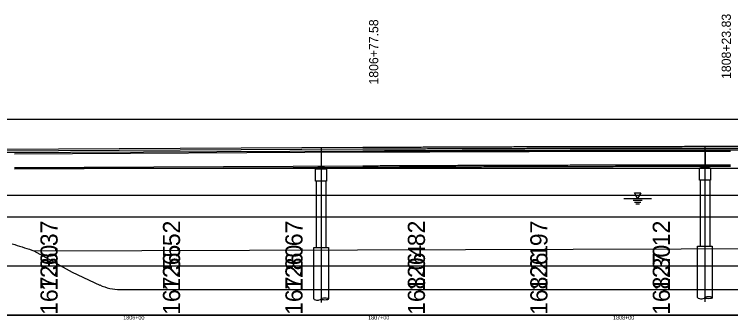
# Model space of a CAD drawing. Extents: x 2126510 to 2136144, y 865066 to 868066.
# Drawn here: x 2133154.3 to 2133446.8, y 867812.5 to 867937.3 of the extents above; entities that cross this region are included whole.
import ezdxf

# ---------------------------------------------------------------- set-up
doc = ezdxf.new("R2010")
doc.units = 0
for name, color, linetype in [('RD_DTM_BkLn1', 7, 'Continuous'), ('RD_EX_BldgApp', 7, 'Continuous'), ('RD_EX_Bridge', 7, 'Continuous'), ('RD_EX_GuardRail', 7, 'Continuous'), ('RD_EX_H2O', 7, 'Continuous'), ('RD_EX_Misc', 7, 'Continuous'), ('RD_EX_UT', 7, 'Continuous'), ('RD_HC_Data', 7, 'Continuous'), ('RD_HC_txCode', 7, 'Continuous')]:
    doc.layers.add(name, color=color, linetype=linetype)

msp = doc.modelspace()

# ---------------------------------------------------------------- linework, layer by layer
at = {"layer": 'RD_DTM_BkLn1'}
for p, q in [((2132861.9, 867879.34), (2133296.65, 867881.51)), ((2133281.33, 867874.43), (2133277.83, 867874.43)), ((2133277.83, 867874.43), (2133277.83, 867874.09)), ((2133280.91, 867874.72), (2133278.24, 867874.72)), ((2133278.24, 867874.43), (2133280.91, 867874.43)), ((2133281.33, 867874.09), (2133281.33, 867874.43)), ((2133434.58, 867874.9), (2133434.58, 867874.56)), ((2133435.99, 867874.9), (2133434.58, 867874.9)), ((2133434.99, 867874.9), (2133437.66, 867874.9)), ((2133438.08, 867874.9), (2133436.33, 867874.9)), ((2133438.08, 867874.56), (2133438.08, 867874.9)), ((2133277.58, 867869.09), (2133277.58, 867841.96)), ((2133281.58, 867869.09), (2133281.58, 867841.96)), ((2133434.33, 867869.56), (2133434.33, 867842.5)), ((2133438.33, 867869.56), (2133438.33, 867842.5))]:
    msp.add_line(p, q, dxfattribs=at)
for points in [[(2133277.33, 867874.09), (2133281.83, 867874.09), (2133281.83, 867869.09), (2133277.33, 867869.09)], [(2133434.08, 867874.56), (2133438.58, 867874.56), (2133438.58, 867869.56), (2133434.08, 867869.56)]]:
    msp.add_lwpolyline(points, close=True, dxfattribs=at)
for points in [[(2133276.58, 867820.98), (2133276.58, 867841.96), (2133282.58, 867841.96), (2133282.58, 867820.98)], [(2133433.33, 867821.52), (2133433.33, 867842.5), (2133439.33, 867842.5), (2133439.33, 867821.52)]]:
    msp.add_lwpolyline(points, dxfattribs=at)
for centre in [(2133281.08, 867820.98), (2133437.83, 867821.52)]:
    msp.add_ellipse(centre, major_axis=(-1.5, 0), ratio=0.310397, dxfattribs=at)
for centre in [(2133434.83, 867821.52), (2133278.08, 867820.98)]:
    msp.add_ellipse(centre, major_axis=(-1.5, 0), ratio=0.310397, start_param=0, end_param=3.141593, dxfattribs=at)
msp.add_spline([(2133296.65, 867881.51), (2133303.7, 867881.54), (2133310.75, 867881.58), (2133317.8, 867881.61), (2133324.85, 867881.64), (2133331.9, 867881.67), (2133338.95, 867881.69), (2133346, 867881.72), (2133353.05, 867881.74), (2133360.1, 867881.76), (2133367.15, 867881.78), (2133374.2, 867881.8), (2133381.25, 867881.82), (2133388.3, 867881.83), (2133395.35, 867881.85), (2133402.4, 867881.86), (2133409.45, 867881.87), (2133416.5, 867881.88), (2133423.55, 867881.89), (2133430.6, 867881.89), (2133437.65, 867881.9), (2133444.7, 867881.9), (2133451.76, 867881.9), (2133458.81, 867881.9), (2133465.86, 867881.9), (2133472.91, 867881.89), (2133479.96, 867881.89), (2133487.01, 867881.88), (2133494.06, 867881.87), (2133501.11, 867881.86), (2133508.16, 867881.85), (2133515.21, 867881.84), (2133522.26, 867881.82), (2133529.31, 867881.8), (2133536.36, 867881.79), (2133543.41, 867881.77), (2133550.46, 867881.75), (2133557.51, 867881.72), (2133564.56, 867881.7), (2133571.61, 867881.67), (2133578.66, 867881.64), (2133585.71, 867881.62), (2133592.76, 867881.58), (2133599.81, 867881.55), (2133606.86, 867881.52), (2133613.91, 867881.48), (2133620.96, 867881.45), (2133628.01, 867881.41), (2133635.06, 867881.37), (2133642.11, 867881.32), (2133649.16, 867881.28)], degree=3, dxfattribs=at)
at = {"layer": 'RD_EX_BldgApp'}
for p, q in [((2133407.51, 867864.29), (2133410.13, 867864.29)), ((2133408.82, 867862.01), (2133407.51, 867864.29)), ((2133410.13, 867864.29), (2133408.82, 867862.01)), ((2133403.2, 867862.01), (2133414.45, 867862.01)), ((2133406.95, 867861.26), (2133410.7, 867861.26)), ((2133407.51, 867860.51), (2133410.13, 867860.51)), ((2133408.07, 867859.76), (2133409.57, 867859.76))]:
    msp.add_line(p, q, dxfattribs=at)
at = {"layer": 'RD_EX_Bridge'}
for p, q in [((2133278.24, 867874.72), (2133278.24, 867874.43)), ((2133280.91, 867874.43), (2133280.91, 867874.72)), ((2133434.99, 867875.19), (2133434.99, 867874.9)), ((2133435.99, 867875.19), (2133435.99, 867874.9)), ((2133436.66, 867874.9), (2133436.66, 867875.19)), ((2133437.66, 867874.9), (2133437.66, 867875.19))]:
    msp.add_line(p, q, dxfattribs=at)
at = {"layer": 'RD_EX_GuardRail'}
for p, q in [((2135251.98, 867894.32), (2130671.73, 867894.32)), ((2135251.98, 867874.32), (2133154.4, 867874.32)), ((2135251.98, 867854.32), (2130671.73, 867854.32)), ((2135251.98, 867834.32), (2130671.73, 867834.32)), ((2135251.98, 867814.32), (2130671.73, 867814.32))]:
    msp.add_line(p, q, dxfattribs=at)
at = {"layer": 'RD_EX_H2O'}
msp.add_line((2133197.59, 867824.82), (2133515.91, 867824.82), dxfattribs=at)
for points in [[(2133153.47, 867843.5), (2133154.47, 867843.18), (2133155.47, 867842.86), (2133156.47, 867842.53), (2133157.47, 867842.21), (2133158.47, 867841.89), (2133159.47, 867841.57), (2133160.47, 867841.25), (2133161.47, 867840.92), (2133162.31, 867840.65)], [(2133162.31, 867840.65), (2133177.95, 867831.86), (2133189.2, 867826.66)]]:
    msp.add_lwpolyline(points, dxfattribs=at)
msp.add_arc((2133197.59, 867844.82), 20, 245.2113, 270, dxfattribs=at)
at = {"layer": 'RD_EX_Misc'}
for p, q in [((2132116.01, 867877.03), (2133296.65, 867882.93)), ((2131523, 867814.32), (2135677.25, 867814.32))]:
    msp.add_line(p, q, dxfattribs=at)
for points in [[(2131430.13, 867814.32), (2131430.13, 867863.32), (2136143.96, 867863.32)], [(2133162.33, 867840.65), (2133558.75, 867841.84)]]:
    msp.add_lwpolyline(points, dxfattribs=at)
msp.add_spline([(2133296.65, 867882.93), (2133303.7, 867882.97), (2133310.75, 867883), (2133317.8, 867883.03), (2133324.85, 867883.06), (2133331.9, 867883.09), (2133338.95, 867883.12), (2133346, 867883.14), (2133353.05, 867883.16), (2133360.1, 867883.19), (2133367.15, 867883.21), (2133374.2, 867883.23), (2133381.25, 867883.24), (2133388.3, 867883.26), (2133395.35, 867883.27), (2133402.4, 867883.28), (2133409.45, 867883.29), (2133416.5, 867883.3), (2133423.55, 867883.31), (2133430.6, 867883.32), (2133437.65, 867883.32), (2133444.7, 867883.32), (2133451.76, 867883.32), (2133458.81, 867883.32), (2133465.86, 867883.32), (2133472.91, 867883.32), (2133479.96, 867883.31), (2133487.01, 867883.3), (2133494.06, 867883.3), (2133501.11, 867883.29), (2133508.16, 867883.27), (2133515.21, 867883.26), (2133522.26, 867883.25), (2133529.31, 867883.23), (2133536.36, 867883.21), (2133543.41, 867883.19), (2133550.46, 867883.17), (2133557.51, 867883.15), (2133564.56, 867883.12), (2133571.61, 867883.1), (2133578.66, 867883.07), (2133585.71, 867883.04), (2133592.76, 867883.01), (2133599.81, 867882.98), (2133606.86, 867882.94), (2133613.91, 867882.91), (2133620.96, 867882.87), (2133628.01, 867882.83), (2133635.06, 867882.79), (2133642.11, 867882.75), (2133649.16, 867882.7)], degree=3, dxfattribs=at)
at = {"layer": 'RD_EX_UT'}
msp.add_line((2132116.01, 867876.33), (2133296.65, 867882.24), dxfattribs=at)
msp.add_spline([(2133296.65, 867882.24), (2133303.7, 867882.27), (2133310.75, 867882.3), (2133317.8, 867882.34), (2133324.85, 867882.37), (2133331.9, 867882.39), (2133338.95, 867882.42), (2133346, 867882.45), (2133353.05, 867882.47), (2133360.1, 867882.49), (2133367.15, 867882.51), (2133374.2, 867882.53), (2133381.25, 867882.55), (2133388.3, 867882.56), (2133395.35, 867882.57), (2133402.4, 867882.59), (2133409.45, 867882.6), (2133416.5, 867882.61), (2133423.55, 867882.61), (2133430.6, 867882.62), (2133437.65, 867882.62), (2133444.7, 867882.63), (2133451.76, 867882.63), (2133458.81, 867882.63), (2133465.86, 867882.62), (2133472.91, 867882.62), (2133479.96, 867882.62), (2133487.01, 867882.61), (2133494.06, 867882.6), (2133501.11, 867882.59), (2133508.16, 867882.58), (2133515.21, 867882.56), (2133522.26, 867882.55), (2133529.31, 867882.53), (2133536.36, 867882.52), (2133543.41, 867882.5), (2133550.46, 867882.47), (2133557.51, 867882.45), (2133564.56, 867882.43), (2133571.61, 867882.4), (2133578.66, 867882.37), (2133585.71, 867882.34), (2133592.76, 867882.31), (2133599.81, 867882.28), (2133606.86, 867882.25), (2133613.91, 867882.21), (2133620.96, 867882.17), (2133628.01, 867882.13), (2133635.06, 867882.09), (2133642.11, 867882.05), (2133649.16, 867882.01)], degree=3, dxfattribs=at)
at = {"layer": 'RD_HC_Data'}
for p, q in [((2133279.58, 867882.85), (2133279.58, 867819.55)), ((2133436.33, 867883.32), (2133436.33, 867819.76))]:
    msp.add_line(p, q, dxfattribs=at)
at = {"layer": 'RD_HC_txCode'}
for p, q in [((2133154.4, 867880.3), (2133296.65, 867881.01)), ((2133436.24, 867881.89), (2133436.24, 867875.19)), ((2133436.41, 867881.9), (2133436.41, 867875.19)), ((2133154.4, 867874.67), (2133296.65, 867875.39)), ((2133154.4, 867874.09), (2133296.65, 867874.8))]:
    msp.add_line(p, q, dxfattribs=at)
for points in [[(2133296.65, 867881.01), (2133303.7, 867881.05), (2133310.75, 867881.08), (2133317.8, 867881.11), (2133324.85, 867881.14), (2133331.9, 867881.17), (2133338.95, 867881.19), (2133346, 867881.22), (2133353.05, 867881.24), (2133360.1, 867881.26), (2133367.15, 867881.28), (2133374.2, 867881.3), (2133381.25, 867881.32), (2133388.3, 867881.33), (2133395.35, 867881.35), (2133402.4, 867881.36), (2133409.45, 867881.37), (2133416.5, 867881.38), (2133423.55, 867881.39), (2133430.6, 867881.39), (2133437.65, 867881.4), (2133444.7, 867881.4), (2133446.74, 867881.4)], [(2133296.65, 867875.39), (2133303.7, 867875.42), (2133310.75, 867875.45), (2133317.8, 867875.48), (2133324.85, 867875.51), (2133331.9, 867875.54), (2133338.95, 867875.57), (2133346, 867875.59), (2133353.05, 867875.62), (2133360.1, 867875.64), (2133367.15, 867875.66), (2133374.2, 867875.68), (2133381.25, 867875.69), (2133388.3, 867875.71), (2133395.35, 867875.72), (2133402.4, 867875.74), (2133409.45, 867875.75), (2133416.5, 867875.75), (2133423.55, 867875.76), (2133430.6, 867875.77), (2133437.65, 867875.77), (2133444.7, 867875.77), (2133446.74, 867875.78)], [(2133296.65, 867874.8), (2133303.7, 867874.84), (2133310.75, 867874.87), (2133317.8, 867874.9), (2133324.85, 867874.93), (2133331.9, 867874.96), (2133338.95, 867874.99), (2133346, 867875.01), (2133353.05, 867875.03), (2133360.1, 867875.06), (2133367.15, 867875.08), (2133374.2, 867875.09), (2133381.25, 867875.11), (2133388.3, 867875.13), (2133395.35, 867875.14), (2133402.4, 867875.15), (2133409.45, 867875.16), (2133416.5, 867875.17), (2133423.55, 867875.18), (2133430.6, 867875.18), (2133437.65, 867875.19), (2133444.7, 867875.19), (2133446.74, 867875.19)]]:
    msp.add_spline(points, degree=3, dxfattribs=at)

# ---------------------------------------------------------------- texts
at = {"layer": 'RD_EX_Misc'}
for s, height, p in [('1808+23.83', 3.75, (2133446.89, 867910.84)), ('1806+77.58', 3.75, (2133302.93, 867908.55)), ('126.37', 7, (2133172, 867824.32)), ('126.52', 7, (2133222, 867824.32)), ('126.67', 7, (2133272, 867824.32)), ('126.82', 7, (2133322, 867824.32)), ('126.97', 7, (2133372, 867824.32)), ('127.12', 7, (2133422, 867824.32)), ('167.30', 7, (2133172, 867814.47)), ('167.55', 7, (2133222, 867814.47)), ('167.80', 7, (2133272, 867814.47)), ('168.04', 7, (2133322, 867814.47)), ('168.21', 7, (2133372, 867814.47)), ('168.30', 7, (2133422, 867814.47))]:
    msp.add_text(s, height=height, rotation=90, dxfattribs=at).set_placement(p)
for s, p in [('1806+00', (2133198.79, 867812.52)), ('1807+00', (2133298.79, 867812.52)), ('1808+00', (2133398.79, 867812.52))]:
    msp.add_text(s, height=1.6, dxfattribs=at).set_placement(p)

doc.saveas('drawing.dxf')
